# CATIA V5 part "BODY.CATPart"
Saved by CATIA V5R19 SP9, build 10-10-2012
Part number: BODY
Material "POM": density 1390 kg/m3
Bounding box of the stored display mesh (mm): x -38.906 to -19.5, y -9.668 to 2.868, z -30 to 29
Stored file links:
  C:\Users\m.zaborsky\Desktop\BODY.CATPart
  N:\CAD-Daten\Catia\Daimler-Chrysler\Projekt-Nr-13014-DHS80Z\06-R5_PROD_WERK-prod_plant\KONSTRUKTION_002.0_#MASTER_Neues_Design_HUF\13014_38_KLAPPE_20140407.CATPart
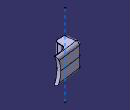
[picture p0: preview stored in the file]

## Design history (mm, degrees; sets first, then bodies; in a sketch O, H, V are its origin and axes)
Set1
  Line1 "AXIS": stored without definition
Body1 (main body)
Body2 "BODY"
  Solid1: solid without history
  Fillet1: radius 2, on edge [face of Solid1 | face of Solid1] (x5)
  Fillet2: radius 3, on edge [face of Solid1 | face of Solid1] (x2)
  Fillet3: radius 0.2, on edge [face of Solid1 | face of Solid1]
